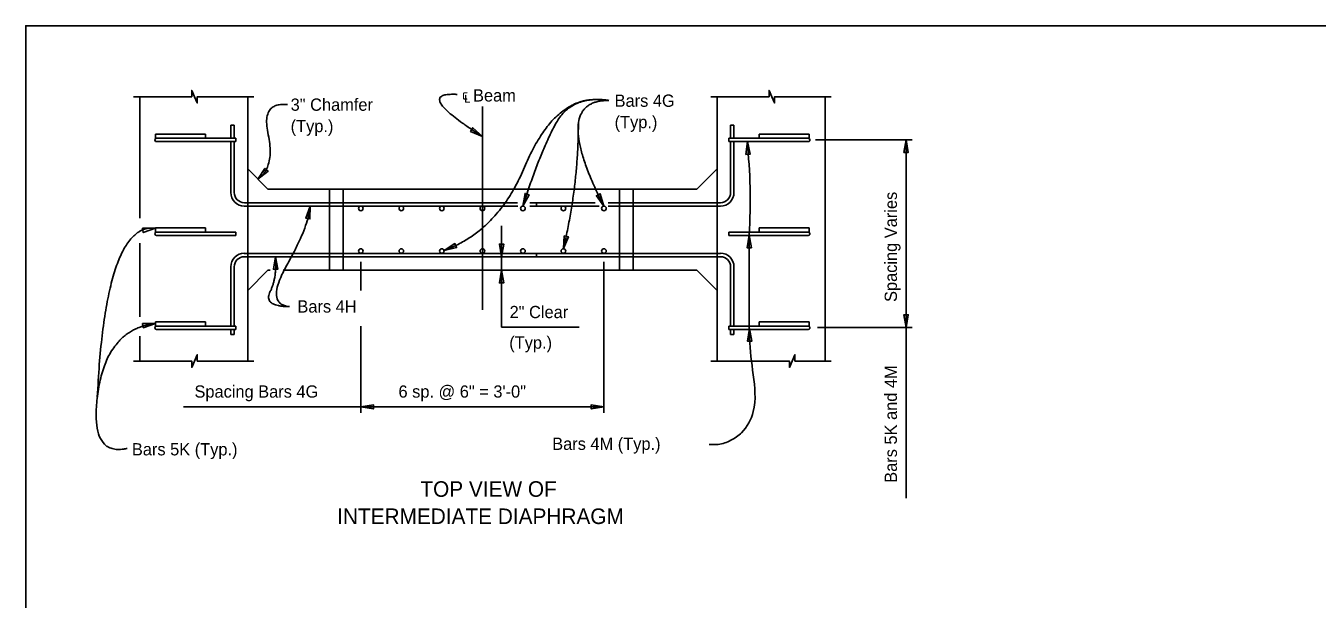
# Model space of a CAD drawing. Extents: x 0 to 54.1, y -6.1 to 22.7.
# Drawn here: x 0.01 to 15.95, y 13.9 to 20.98 of the extents above; entities that cross this region are included whole.
import ezdxf

# ---------------------------------------------------------------- set-up
doc = ezdxf.new("R2010")
doc.units = 0
for name, color, linetype in [('ActivePts-ConstElements', 7, 'Continuous'), ('BeamConc', 7, 'Continuous'), ('CL_Major', 7, 'Continuous'), ('Dimension', 7, 'Continuous'), ('Miscellaneous', 7, 'Continuous'), ('Rebar', 7, 'Continuous'), ('TextStructures', 7, 'Continuous')]:
    doc.layers.add(name, color=color, linetype=linetype)

msp = doc.modelspace()

# ---------------------------------------------------------------- linework, layer by layer
at = {"layer": 'ActivePts-ConstElements'}
msp.add_lwpolyline([(0.012, 1.54), (30.777, 1.54), (30.777, 20.982), (0.012, 20.982)], close=True, dxfattribs=at)
at = {"layer": 'BeamConc'}
for p, q in [((1.417, 18.609), (1.417, 20.106)), ((2.75, 16.843), (2.75, 20.106)), ((8.542, 20.106), (8.542, 16.843)), ((9.875, 20.106), (9.875, 16.843)), ((3, 18.965), (2.75, 19.215)), ((8.542, 19.215), (8.292, 18.965)), ((8.292, 18.965), (3, 18.965)), ((1.417, 17.39), (1.417, 18.3)), ((3, 17.965), (2.75, 17.715)), ((3.028, 17.965), (3, 17.965)), ((8.292, 17.965), (3.187, 17.965)), ((8.542, 17.715), (8.292, 17.965)), ((1.417, 16.843), (1.417, 17.15))]:
    msp.add_line(p, q, dxfattribs=at)
at = {"layer": 'CL_Major'}
msp.add_line((5.646, 17.475), (5.646, 19.986), dxfattribs=at)
at = {"layer": 'Dimension'}
for p, q in [((9.757, 19.576), (10.951, 19.576)), ((10.875, 19.576), (10.875, 15.15)), ((5.884, 18.513), (5.884, 17.26)), ((4.146, 18.069), (4.146, 17.714)), ((7.146, 18.069), (7.146, 16.203)), ((4.146, 17.274), (4.146, 16.203)), ((5.884, 17.26), (6.84, 17.26)), ((9.783, 17.259), (10.951, 17.259)), ((1.957, 16.279), (7.146, 16.279))]:
    msp.add_line(p, q, dxfattribs=at)
for points in [[(2.826, 20.106), (2.127, 20.106), (2.127, 20.029), (2.093, 20.106), (2.059, 20.184), (2.059, 20.106), (1.341, 20.106)], [(9.951, 20.106), (9.252, 20.106), (9.252, 20.029), (9.218, 20.106), (9.184, 20.184), (9.184, 20.106), (8.466, 20.106)], [(2.826, 16.843), (2.127, 16.843), (2.127, 16.921), (2.093, 16.843), (2.059, 16.766), (2.059, 16.843), (1.341, 16.843)], [(9.951, 16.843), (9.504, 16.843), (9.504, 16.921), (9.47, 16.843), (9.436, 16.766), (9.436, 16.843), (8.466, 16.843)]]:
    msp.add_lwpolyline(points, dxfattribs=at)
for points in [[(5.646, 19.617), (5.528, 19.723), (5.5, 19.679)], [(8.916, 19.553), (8.899, 19.395), (8.952, 19.399)], [(10.875, 19.576), (10.902, 19.419), (10.849, 19.419)], [(2.875, 19.09), (2.963, 19.222), (3.001, 19.186)], [(6.146, 18.757), (6.173, 18.913), (6.223, 18.895)], [(7.146, 18.756), (7.053, 18.885), (7.101, 18.908)], [(3.521, 18.757), (3.466, 18.608), (3.518, 18.598)], [(3.521, 18.757), (3.521, 18.756), (3.521, 18.756)], [(1.611, 18.483), (1.453, 18.483), (1.462, 18.43)], [(6.646, 18.231), (6.708, 18.377), (6.656, 18.389)], [(8.94, 18.399), (8.913, 18.243), (8.966, 18.243)], [(5.174, 18.21), (5.328, 18.244), (5.308, 18.293)], [(5.884, 18.132), (5.91, 18.288), (5.857, 18.288)], [(3.094, 18.132), (3.12, 17.976), (3.067, 17.976)], [(5.884, 17.965), (5.857, 17.809), (5.91, 17.809)], [(10.875, 17.258), (10.849, 17.415), (10.902, 17.415)], [(1.611, 17.306), (1.453, 17.306), (1.462, 17.254)], [(8.944, 17.245), (8.918, 17.089), (8.971, 17.089)], [(8.944, 17.245), (8.944, 17.244), (8.944, 17.244)], [(4.146, 16.279), (4.302, 16.305), (4.302, 16.252)], [(7.146, 16.279), (6.99, 16.252), (6.99, 16.305)]]:
    msp.add_lwpolyline(points, close=True, dxfattribs=at)
for points in [[(5.646, 19.617), (4.78, 20.165), (5.333, 20.135)], [(2.875, 19.09), (3.089, 19.242), (2.915, 20.044), (3.24, 20.009)], [(5.174, 18.21), (5.835, 18.446), (6.502, 20.035), (6.997, 20.07)], [(6.146, 18.757), (6.351, 19.399), (6.742, 20.131), (7.207, 20.061)], [(7.146, 18.757), (6.477, 20.061), (7.207, 20.061)], [(6.646, 18.231), (6.831, 19.014), (6.831, 19.781)], [(3.521, 18.757), (3.507, 18.514), (2.961, 17.545), (3.266, 17.515)], [(1.611, 18.483), (0.998, 18.561), (0.894, 16.4)], [(3.094, 18.132), (3.113, 17.875), (2.939, 17.52), (3.266, 17.515)], [(1.611, 17.306), (1.013, 17.241), (0.789, 15.656), (1.263, 15.766)]]:
    msp.add_open_spline(points, degree=2, dxfattribs=at)
for points in [[(8.916, 19.553), (8.95, 18.986), (8.94, 18.397)], [(8.94, 18.399), (8.94, 17.862), (8.94, 17.235)], [(8.944, 17.245), (8.944, 17.124), (8.989, 16.674), (8.989, 16.22), (8.845, 15.959), (8.711, 15.865), (8.558, 15.815), (8.446, 15.815)]]:
    msp.add_spline(points, degree=3, dxfattribs=at)
at = {"layer": 'Miscellaneous'}
for p, q in [((3.76, 18.965), (3.76, 17.965)), ((3.927, 18.965), (3.927, 17.965)), ((7.338, 18.965), (7.338, 17.965)), ((7.505, 18.965), (7.505, 17.965))]:
    msp.add_line(p, q, dxfattribs=at)
at = {"layer": 'Rebar'}
for p, q in [((1.611, 19.593), (1.611, 19.646)), ((1.611, 19.646), (2.231, 19.646)), ((2.231, 19.593), (2.231, 19.646)), ((2.542, 19.757), (2.584, 19.757)), ((2.542, 19.593), (2.542, 19.757)), ((2.584, 19.593), (2.584, 19.757)), ((8.75, 19.757), (8.709, 19.757)), ((8.709, 19.757), (8.709, 19.593)), ((8.75, 19.757), (8.75, 19.593)), ((9.681, 19.646), (9.061, 19.646)), ((9.061, 19.593), (9.061, 19.646)), ((9.681, 19.593), (9.681, 19.646)), ((1.611, 19.593), (2.604, 19.593)), ((1.625, 19.552), (2.604, 19.552)), ((2.542, 18.923), (2.542, 19.552)), ((2.584, 18.923), (2.584, 19.552)), ((2.604, 19.552), (2.604, 19.593)), ((9.681, 19.593), (8.688, 19.593)), ((8.688, 19.552), (8.688, 19.593)), ((9.667, 19.552), (8.688, 19.552)), ((8.709, 19.552), (8.709, 18.923)), ((8.75, 19.552), (8.75, 18.923)), ((6.083, 18.757), (2.708, 18.757)), ((6.08, 18.798), (2.709, 18.798)), ((7.037, 18.798), (6.233, 18.798)), ((7.087, 18.757), (6.233, 18.757)), ((6.313, 18.757), (6.313, 18.798)), ((8.584, 18.798), (7.197, 18.798)), ((8.584, 18.757), (7.197, 18.757)), ((1.611, 18.435), (1.611, 18.487)), ((1.611, 18.487), (2.231, 18.487)), ((2.231, 18.435), (2.231, 18.487)), ((9.681, 18.487), (9.061, 18.487)), ((9.061, 18.435), (9.061, 18.487)), ((9.681, 18.435), (9.681, 18.487)), ((1.611, 18.435), (2.604, 18.435)), ((1.625, 18.393), (2.604, 18.393)), ((2.604, 18.393), (2.604, 18.435)), ((9.681, 18.435), (8.688, 18.435)), ((8.688, 18.393), (8.688, 18.435)), ((9.667, 18.393), (8.688, 18.393)), ((8.584, 18.173), (2.708, 18.173)), ((6.313, 18.132), (6.313, 18.173)), ((8.584, 18.132), (2.709, 18.132)), ((2.542, 18.007), (2.542, 17.276)), ((2.584, 18.007), (2.584, 17.276)), ((8.709, 17.276), (8.709, 18.007)), ((8.75, 17.276), (8.75, 18.007)), ((1.611, 17.276), (1.611, 17.328)), ((1.611, 17.328), (2.231, 17.328)), ((1.611, 17.276), (2.604, 17.276)), ((1.625, 17.235), (2.604, 17.235)), ((2.231, 17.276), (2.231, 17.328)), ((2.542, 17.235), (2.542, 17.173)), ((2.584, 17.235), (2.584, 17.173)), ((2.604, 17.235), (2.604, 17.276)), ((9.681, 17.276), (8.688, 17.276)), ((8.688, 17.235), (8.688, 17.276)), ((9.667, 17.235), (8.688, 17.235)), ((8.709, 17.173), (8.709, 17.235)), ((8.75, 17.173), (8.75, 17.235)), ((9.681, 17.328), (9.061, 17.328)), ((9.061, 17.276), (9.061, 17.328)), ((9.681, 17.276), (9.681, 17.328)), ((2.542, 17.173), (2.584, 17.173)), ((8.75, 17.173), (8.709, 17.173))]:
    msp.add_line(p, q, dxfattribs=at)
for centre in [(4.146, 18.728), (4.646, 18.728), (5.146, 18.728), (5.646, 18.728), (6.146, 18.728), (6.646, 18.728), (7.146, 18.728), (4.146, 18.202), (4.646, 18.202), (5.146, 18.202), (5.646, 18.202), (6.146, 18.202), (6.646, 18.202), (7.146, 18.202)]:
    msp.add_circle(centre, 0.0286, dxfattribs=at)
for centre, radius, start, end in [((1.625, 19.573), 0.0209, 81.4319, 269.9425), ((9.667, 19.573), 0.0209, 270.0575, 98.5681), ((2.709, 18.923), 0.167, 180, 270), ((2.709, 18.923), 0.125, 180, 270), ((8.584, 18.923), 0.125, 270, 360), ((8.584, 18.923), 0.167, 270, 360), ((1.625, 18.414), 0.0209, 81.4319, 269.9425), ((9.667, 18.414), 0.0209, 270.0575, 98.5681), ((2.709, 18.007), 0.167, 90, 180), ((8.584, 18.007), 0.167, 0, 90), ((2.709, 18.007), 0.125, 90, 180), ((8.584, 18.007), 0.125, 0, 90), ((1.625, 17.255), 0.0209, 81.4319, 269.9425), ((9.667, 17.255), 0.0209, 270.0575, 98.5681)]:
    msp.add_arc(centre, radius, start, end, dxfattribs=at)

# ---------------------------------------------------------------- texts
at = {"layer": 'Dimension'}
for s, height, p in [('3" Chamfer', 0.1512, (3.28, 19.933)), ('Bars 4G', 0.1512, (7.278, 19.982)), ('(Typ.)', 0.1512, (3.28, 19.669)), ('(Typ.)', 0.1512, (7.278, 19.718)), ('TOP VIEW OF', 0.192, (4.881, 15.168)), ('INTERMEDIATE DIAPHRAGM', 0.192, (3.854, 14.832))]:
    msp.add_text(s, height=height, dxfattribs=at).set_placement(p)
at = {"layer": 'TextStructures'}
for s, p in [('℄ Beam', (5.393, 20.047)), ('Bars 4H', (3.364, 17.442)), ('2" Clear', (5.982, 17.373)), ('(Typ.)', (5.978, 16.996)), ('Spacing Bars 4G', (2.093, 16.392)), ('6 sp. @ 6" = 3\'-0"', (4.611, 16.392)), ('Bars 5K (Typ.)', (1.321, 15.679))]:
    msp.add_text(s, height=0.1512, dxfattribs=at).set_placement(p)
for s, rotation, p in [('Spacing Varies', 90, (10.762, 17.573)), ('Bars 5K and 4M', 90, (10.762, 15.341)), ('Bars 4M (Typ.)', 360, (6.508, 15.747))]:
    msp.add_text(s, height=0.1512, rotation=rotation, dxfattribs=at).set_placement(p)

doc.saveas('drawing.dxf')
